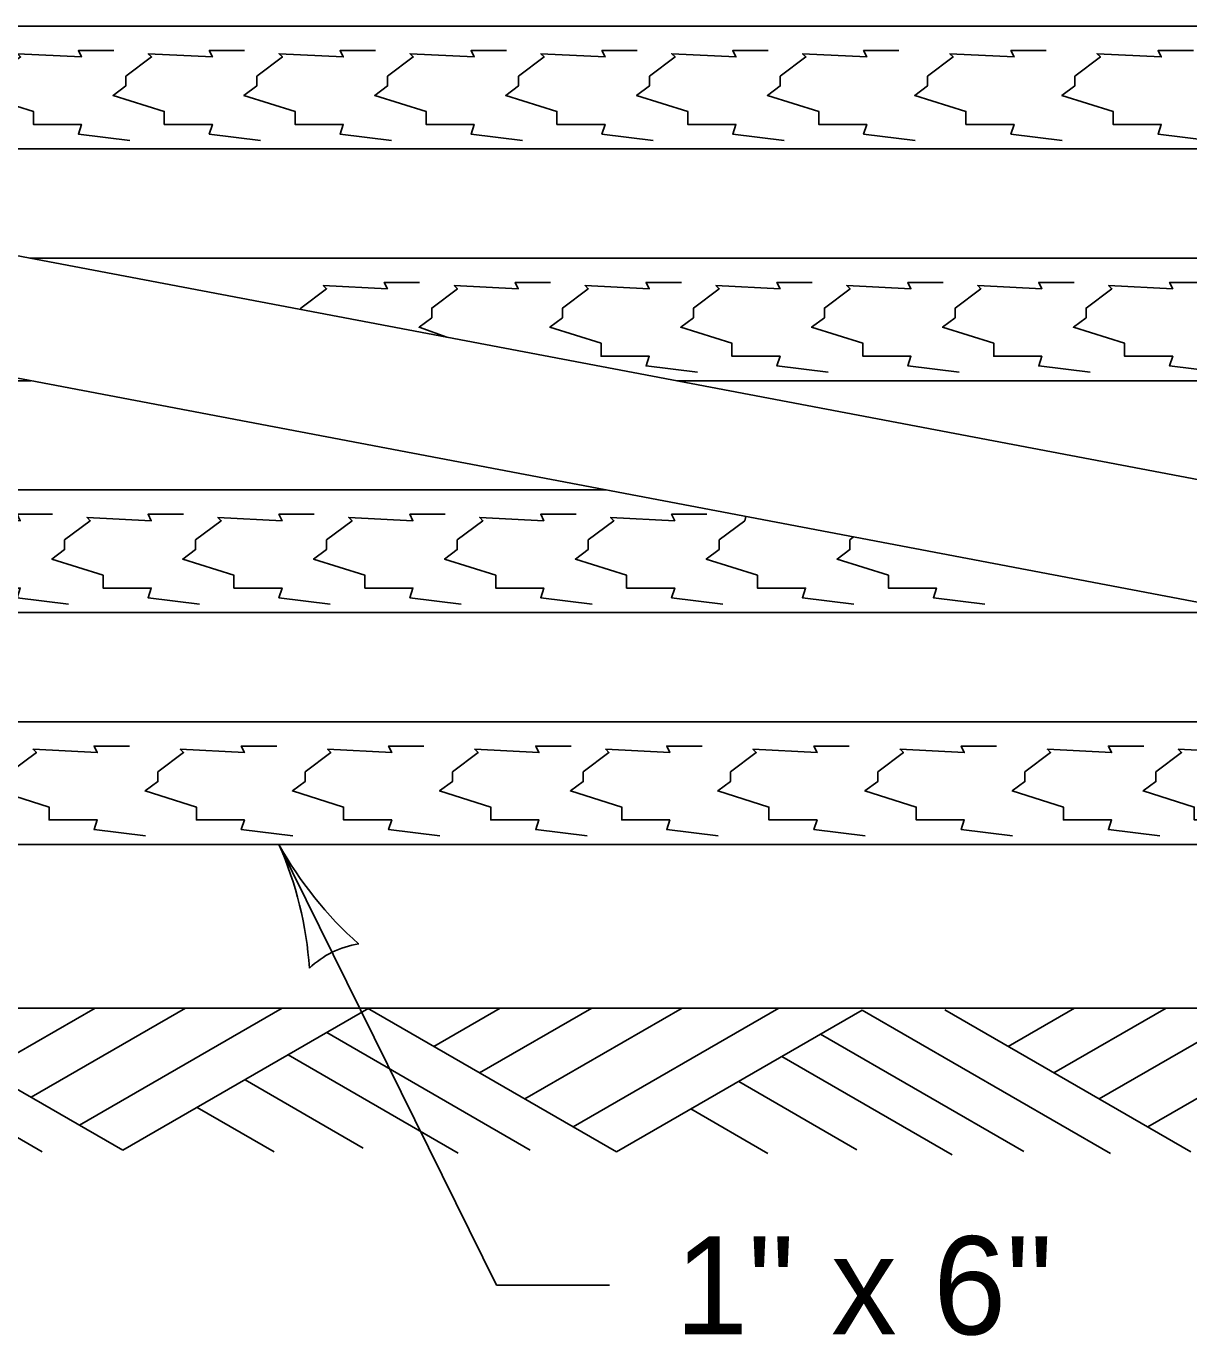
# Model space of a CAD drawing. Extents: x 49991.4 to 50021, y 49987.6 to 50011.4.
# Drawn here: x 50004.158 to 50004.869, y 50009.383 to 50010.183 of the extents above; entities that cross this region are included whole.
import ezdxf

# ---------------------------------------------------------------- set-up
doc = ezdxf.new("R2010")
doc.units = 0
for name, color, linetype in [('Level 1', 7, 'Continuous'), ('Level 2', 7, 'Continuous'), ('Level 3', 7, 'Continuous')]:
    doc.layers.add(name, color=color, linetype=linetype)

msp = doc.modelspace()

# ---------------------------------------------------------------- linework, layer by layer
at = {"layer": 'Level 1'}
for p, q in [((50003.3389, 50010.1834), (50005.6927, 50010.1834)), ((50005.6552, 50009.7582), (50003.4138, 50010.1834)), ((50005.6552, 50009.6833), (50003.4139, 50010.1085)), ((50003.80916, 50010.1084), (50005.6552, 50010.1084)), ((50004.16076, 50010.0417), (50005.6552, 50010.0417)), ((50003.4139, 50009.9667), (50004.16135, 50009.9667)), ((50004.55611, 50009.9667), (50005.6552, 50009.9667)), ((50003.4139, 50009.9), (50004.51294, 50009.9)), ((50003.4139, 50009.825), (50004.90828, 50009.825)), ((50003.4139, 50009.7582), (50005.26039, 50009.7582)), ((50003.3389, 50009.6833), (50005.7302, 50009.6833)), ((50001.4073, 50009.5833), (50004.5539, 50009.5833)), ((50004.0161, 50009.5833), (50004.1683, 50009.4954)), ((50004.0671, 50009.5833), (50004.21755, 50009.49641)), ((50004.20066, 50009.5833), (50004.13384, 50009.54475)), ((50004.25594, 50009.5833), (50004.16149, 50009.52879)), ((50004.315, 50009.5833), (50004.1911, 50009.5117)), ((50004.368, 50009.5833), (50004.21755, 50009.49641)), ((50004.3672, 50009.5833), (50004.5194, 50009.4954)), ((50004.44818, 50009.5833), (50004.40767, 50009.55993)), ((50004.50419, 50009.5833), (50004.43566, 50009.54376)), ((50004.55948, 50009.5833), (50004.4633, 50009.5278)), ((50004.61853, 50009.5833), (50004.4929, 50009.5107)), ((50004.6694, 50009.58207), (50004.51937, 50009.49542)), ((50004.5539, 50009.5833), (50007.5434, 50009.5833)), ((50004.6694, 50009.58207), (50004.8212, 50009.4944)), ((50004.72, 50009.5823), (50004.87045, 50009.49541)), ((50004.79928, 50009.5833), (50004.75875, 50009.55992)), ((50004.85529, 50009.5833), (50004.78674, 50009.54375)), ((50004.91058, 50009.5833), (50004.81439, 50009.52779)), ((50004.96963, 50009.5833), (50004.844, 50009.5107)), ((50004.34226, 50009.56843), (50004.4666, 50009.4966)), ((50004.64406, 50009.56743), (50004.7684, 50009.4956)), ((50004.3186, 50009.55477), (50004.4226, 50009.4947)), ((50004.6204, 50009.55377), (50004.7244, 50009.4937)), ((50004.29226, 50009.53956), (50004.3645, 50009.4978)), ((50004.59406, 50009.53856), (50004.6663, 50009.4968)), ((50004.26301, 50009.52267), (50004.3101, 50009.4954)), ((50004.56481, 50009.52167), (50004.6119, 50009.4944))]:
    msp.add_line(p, q, dxfattribs=at)
for points in [[(50004.2218, 50010.1136), (50004.1904, 50010.1175), (50004.1923, 50010.1234), (50004.1629, 50010.1234), (50004.1629, 50010.1313), (50004.1316, 50010.1411), (50004.1394, 50010.1469), (50004.1394, 50010.1528), (50004.1551, 50010.1646), (50004.1531, 50010.1666), (50004.1923, 50010.1646), (50004.1904, 50010.1685), (50004.212, 50010.1685)], [(50004.3018, 50010.1136), (50004.2704, 50010.1175), (50004.2723, 50010.1234), (50004.2429, 50010.1234), (50004.2429, 50010.1313), (50004.2116, 50010.1411), (50004.2194, 50010.1469), (50004.2194, 50010.1528), (50004.2351, 50010.1646), (50004.2331, 50010.1666), (50004.2723, 50010.1646), (50004.2704, 50010.1685), (50004.292, 50010.1685)], [(50004.3818, 50010.1136), (50004.3504, 50010.1175), (50004.3523, 50010.1234), (50004.3229, 50010.1234), (50004.3229, 50010.1313), (50004.2916, 50010.1411), (50004.2994, 50010.1469), (50004.2994, 50010.1528), (50004.3151, 50010.1646), (50004.3131, 50010.1666), (50004.3523, 50010.1646), (50004.3504, 50010.1685), (50004.372, 50010.1685)], [(50004.4618, 50010.1136), (50004.4304, 50010.1175), (50004.4323, 50010.1234), (50004.4029, 50010.1234), (50004.4029, 50010.1313), (50004.3716, 50010.1411), (50004.3794, 50010.1469), (50004.3794, 50010.1528), (50004.3951, 50010.1646), (50004.3931, 50010.1666), (50004.4323, 50010.1646), (50004.4304, 50010.1685), (50004.452, 50010.1685)], [(50004.5418, 50010.1136), (50004.5104, 50010.1175), (50004.5123, 50010.1234), (50004.4829, 50010.1234), (50004.4829, 50010.1313), (50004.4516, 50010.1411), (50004.4594, 50010.1469), (50004.4594, 50010.1528), (50004.4751, 50010.1646), (50004.4731, 50010.1666), (50004.5123, 50010.1646), (50004.5104, 50010.1685), (50004.532, 50010.1685)], [(50004.6218, 50010.1136), (50004.5904, 50010.1175), (50004.5923, 50010.1234), (50004.5629, 50010.1234), (50004.5629, 50010.1313), (50004.5316, 50010.1411), (50004.5394, 50010.1469), (50004.5394, 50010.1528), (50004.5551, 50010.1646), (50004.5531, 50010.1666), (50004.5923, 50010.1646), (50004.5904, 50010.1685), (50004.612, 50010.1685)], [(50004.7018, 50010.1136), (50004.6704, 50010.1175), (50004.6723, 50010.1234), (50004.6429, 50010.1234), (50004.6429, 50010.1313), (50004.6116, 50010.1411), (50004.6194, 50010.1469), (50004.6194, 50010.1528), (50004.6351, 50010.1646), (50004.6331, 50010.1666), (50004.6723, 50010.1646), (50004.6704, 50010.1685), (50004.692, 50010.1685)], [(50004.7918, 50010.1136), (50004.7604, 50010.1175), (50004.7623, 50010.1234), (50004.7329, 50010.1234), (50004.7329, 50010.1313), (50004.7016, 50010.1411), (50004.7094, 50010.1469), (50004.7094, 50010.1528), (50004.7251, 50010.1646), (50004.7231, 50010.1666), (50004.7623, 50010.1646), (50004.7604, 50010.1685), (50004.782, 50010.1685)], [(50004.8818, 50010.1136), (50004.8504, 50010.1175), (50004.8523, 50010.1234), (50004.8229, 50010.1234), (50004.8229, 50010.1313), (50004.7916, 50010.1411), (50004.7994, 50010.1469), (50004.7994, 50010.1528), (50004.8151, 50010.1646), (50004.8131, 50010.1666), (50004.8523, 50010.1646), (50004.8504, 50010.1685), (50004.872, 50010.1685)], [(50004.3264, 50010.01028), (50004.3264, 50010.0111), (50004.3421, 50010.0229), (50004.3401, 50010.0249), (50004.3793, 50010.0229), (50004.3774, 50010.0268), (50004.399, 50010.0268)], [(50004.4157, 50009.99334), (50004.3986, 50009.9994), (50004.4064, 50010.0052), (50004.4064, 50010.0111), (50004.4221, 50010.0229), (50004.4201, 50010.0249), (50004.4593, 50010.0229), (50004.4574, 50010.0268), (50004.479, 50010.0268)], [(50004.5688, 50009.9719), (50004.5374, 50009.9758), (50004.5393, 50009.9817), (50004.5099, 50009.9817), (50004.5099, 50009.9896), (50004.4786, 50009.9994), (50004.4864, 50010.0052), (50004.4864, 50010.0111), (50004.5021, 50010.0229), (50004.5001, 50010.0249), (50004.5393, 50010.0229), (50004.5374, 50010.0268), (50004.559, 50010.0268)], [(50004.6488, 50009.9719), (50004.6174, 50009.9758), (50004.6193, 50009.9817), (50004.5899, 50009.9817), (50004.5899, 50009.9896), (50004.5586, 50009.9994), (50004.5664, 50010.0052), (50004.5664, 50010.0111), (50004.5821, 50010.0229), (50004.5801, 50010.0249), (50004.6193, 50010.0229), (50004.6174, 50010.0268), (50004.639, 50010.0268)], [(50004.7288, 50009.9719), (50004.6974, 50009.9758), (50004.6993, 50009.9817), (50004.6699, 50009.9817), (50004.6699, 50009.9896), (50004.6386, 50009.9994), (50004.6464, 50010.0052), (50004.6464, 50010.0111), (50004.6621, 50010.0229), (50004.6601, 50010.0249), (50004.6993, 50010.0229), (50004.6974, 50010.0268), (50004.719, 50010.0268)], [(50004.8088, 50009.9719), (50004.7774, 50009.9758), (50004.7793, 50009.9817), (50004.7499, 50009.9817), (50004.7499, 50009.9896), (50004.7186, 50009.9994), (50004.7264, 50010.0052), (50004.7264, 50010.0111), (50004.7421, 50010.0229), (50004.7401, 50010.0249), (50004.7793, 50010.0229), (50004.7774, 50010.0268), (50004.799, 50010.0268)], [(50004.8888, 50009.9719), (50004.8574, 50009.9758), (50004.8593, 50009.9817), (50004.8299, 50009.9817), (50004.8299, 50009.9896), (50004.7986, 50009.9994), (50004.8064, 50010.0052), (50004.8064, 50010.0111), (50004.8221, 50010.0229), (50004.8201, 50010.0249), (50004.8593, 50010.0229), (50004.8574, 50010.0268), (50004.879, 50010.0268)], [(50004.1844, 50009.8302), (50004.153, 50009.8341), (50004.1549, 50009.84), (50004.1255, 50009.84), (50004.1255, 50009.8479), (50004.0942, 50009.8577), (50004.102, 50009.8635), (50004.102, 50009.8694), (50004.1177, 50009.8812), (50004.1157, 50009.8832), (50004.1549, 50009.8812), (50004.153, 50009.8851), (50004.1746, 50009.8851)], [(50004.2644, 50009.8302), (50004.233, 50009.8341), (50004.2349, 50009.84), (50004.2055, 50009.84), (50004.2055, 50009.8479), (50004.1742, 50009.8577), (50004.182, 50009.8635), (50004.182, 50009.8694), (50004.1977, 50009.8812), (50004.1957, 50009.8832), (50004.2349, 50009.8812), (50004.233, 50009.8851), (50004.2546, 50009.8851)], [(50004.3444, 50009.8302), (50004.313, 50009.8341), (50004.3149, 50009.84), (50004.2855, 50009.84), (50004.2855, 50009.8479), (50004.2542, 50009.8577), (50004.262, 50009.8635), (50004.262, 50009.8694), (50004.2777, 50009.8812), (50004.2757, 50009.8832), (50004.3149, 50009.8812), (50004.313, 50009.8851), (50004.3346, 50009.8851)], [(50004.4244, 50009.8302), (50004.393, 50009.8341), (50004.3949, 50009.84), (50004.3655, 50009.84), (50004.3655, 50009.8479), (50004.3342, 50009.8577), (50004.342, 50009.8635), (50004.342, 50009.8694), (50004.3577, 50009.8812), (50004.3557, 50009.8832), (50004.3949, 50009.8812), (50004.393, 50009.8851), (50004.4146, 50009.8851)], [(50004.5044, 50009.8302), (50004.473, 50009.8341), (50004.4749, 50009.84), (50004.4455, 50009.84), (50004.4455, 50009.8479), (50004.4142, 50009.8577), (50004.422, 50009.8635), (50004.422, 50009.8694), (50004.4377, 50009.8812), (50004.4357, 50009.8832), (50004.4749, 50009.8812), (50004.473, 50009.8851), (50004.4946, 50009.8851)], [(50004.5844, 50009.8302), (50004.553, 50009.8341), (50004.5549, 50009.84), (50004.5255, 50009.84), (50004.5255, 50009.8479), (50004.4942, 50009.8577), (50004.502, 50009.8635), (50004.502, 50009.8694), (50004.5177, 50009.8812), (50004.5157, 50009.8832), (50004.5549, 50009.8812), (50004.553, 50009.8851), (50004.5746, 50009.8851)], [(50004.6644, 50009.8302), (50004.633, 50009.8341), (50004.6349, 50009.84), (50004.6055, 50009.84), (50004.6055, 50009.8479), (50004.5742, 50009.8577), (50004.582, 50009.8635), (50004.582, 50009.8694), (50004.5977, 50009.8812), (50004.5983, 50009.88381)], [(50004.7444, 50009.8302), (50004.713, 50009.8341), (50004.7149, 50009.84), (50004.6855, 50009.84), (50004.6855, 50009.8479), (50004.6542, 50009.8577), (50004.662, 50009.8635), (50004.662, 50009.8694), (50004.66429, 50009.87129)], [(50004.2314, 50009.6885), (50004.2, 50009.6924), (50004.2019, 50009.6983), (50004.1725, 50009.6983), (50004.1725, 50009.7062), (50004.1412, 50009.716), (50004.149, 50009.7218), (50004.149, 50009.7277), (50004.1647, 50009.7395), (50004.1627, 50009.7415), (50004.2019, 50009.7395), (50004.2, 50009.7434), (50004.2216, 50009.7434)], [(50004.3214, 50009.6885), (50004.29, 50009.6924), (50004.2919, 50009.6983), (50004.2625, 50009.6983), (50004.2625, 50009.7062), (50004.2312, 50009.716), (50004.239, 50009.7218), (50004.239, 50009.7277), (50004.2547, 50009.7395), (50004.2527, 50009.7415), (50004.2919, 50009.7395), (50004.29, 50009.7434), (50004.3116, 50009.7434)], [(50004.4114, 50009.6885), (50004.38, 50009.6924), (50004.3819, 50009.6983), (50004.3525, 50009.6983), (50004.3525, 50009.7062), (50004.3212, 50009.716), (50004.329, 50009.7218), (50004.329, 50009.7277), (50004.3447, 50009.7395), (50004.3427, 50009.7415), (50004.3819, 50009.7395), (50004.38, 50009.7434), (50004.4016, 50009.7434)], [(50004.5014, 50009.6885), (50004.47, 50009.6924), (50004.4719, 50009.6983), (50004.4425, 50009.6983), (50004.4425, 50009.7062), (50004.4112, 50009.716), (50004.419, 50009.7218), (50004.419, 50009.7277), (50004.4347, 50009.7395), (50004.4327, 50009.7415), (50004.4719, 50009.7395), (50004.47, 50009.7434), (50004.4916, 50009.7434)], [(50004.5814, 50009.6885), (50004.55, 50009.6924), (50004.5519, 50009.6983), (50004.5225, 50009.6983), (50004.5225, 50009.7062), (50004.4912, 50009.716), (50004.499, 50009.7218), (50004.499, 50009.7277), (50004.5147, 50009.7395), (50004.5127, 50009.7415), (50004.5519, 50009.7395), (50004.55, 50009.7434), (50004.5716, 50009.7434)], [(50004.6714, 50009.6885), (50004.64, 50009.6924), (50004.6419, 50009.6983), (50004.6125, 50009.6983), (50004.6125, 50009.7062), (50004.5812, 50009.716), (50004.589, 50009.7218), (50004.589, 50009.7277), (50004.6047, 50009.7395), (50004.6027, 50009.7415), (50004.6419, 50009.7395), (50004.64, 50009.7434), (50004.6616, 50009.7434)], [(50004.7614, 50009.6885), (50004.73, 50009.6924), (50004.7319, 50009.6983), (50004.7025, 50009.6983), (50004.7025, 50009.7062), (50004.6712, 50009.716), (50004.679, 50009.7218), (50004.679, 50009.7277), (50004.6947, 50009.7395), (50004.6927, 50009.7415), (50004.7319, 50009.7395), (50004.73, 50009.7434), (50004.7516, 50009.7434)], [(50004.8514, 50009.6885), (50004.82, 50009.6924), (50004.8219, 50009.6983), (50004.7925, 50009.6983), (50004.7925, 50009.7062), (50004.7612, 50009.716), (50004.769, 50009.7218), (50004.769, 50009.7277), (50004.7847, 50009.7395), (50004.7827, 50009.7415), (50004.8219, 50009.7395), (50004.82, 50009.7434), (50004.8416, 50009.7434)], [(50004.9314, 50009.6885), (50004.9, 50009.6924), (50004.9019, 50009.6983), (50004.8725, 50009.6983), (50004.8725, 50009.7062), (50004.8412, 50009.716), (50004.849, 50009.7218), (50004.849, 50009.7277), (50004.8647, 50009.7395), (50004.8627, 50009.7415), (50004.9019, 50009.7395), (50004.9, 50009.7434), (50004.9216, 50009.7434)]]:
    msp.add_lwpolyline(points, dxfattribs=at)
at = {"layer": 'Level 3'}
for p, q in [((50004.313, 50009.6833), (50004.4459, 50009.4139)), ((50004.4459, 50009.4139), (50004.5151, 50009.4139))]:
    msp.add_line(p, q, dxfattribs=at)
for centre, radius, start, end in [((50004.10974, 50009.59324), 0.22232, 3.71399, 23.89749), ((50004.51661, 50009.79656), 0.233, 209.08529, 228.33514), ((50004.36972, 50009.56832), 0.05477, 98.39679, 134.11916)]:
    msp.add_arc(centre, radius, start, end, dxfattribs=at)

# ---------------------------------------------------------------- texts
at = {"layer": 'Level 2'}
msp.add_text('1" x 6"', height=0.06, dxfattribs=at).set_placement((50004.5551, 50009.3839))

doc.saveas('drawing.dxf')
